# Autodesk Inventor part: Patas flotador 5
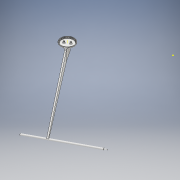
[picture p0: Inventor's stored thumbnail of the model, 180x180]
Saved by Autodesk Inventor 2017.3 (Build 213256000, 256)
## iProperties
Part Number: Patas flotador 5
Material: Plástico ABS
Document SubType Name: Modeling
Designer: PABLO HERNANDEZ
Density: 1.06 g/cm^3
Appearance: Suave - Blanco
Mass: 4.28877 g
Surface Area: 39.5254 cm^2
Volume: 4.04601 cm^3
Author: M.RICO
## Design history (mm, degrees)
sketch "Boceto1"
  geometry: C1 r 16 at (0, 0); 1 further point
  constraints: 1 centre point, 1 coincident
  dimensions: "d0" = 32 diameter of C1
extrude "Extrusión1" new body sketch "Boceto1" distance "d1" = 1; taper "d2" = 0 deg; dims "d93" = 1, "d94" = 0
sketch "Boceto2"
  geometry: C1 r 16 at (0, 0); C2 r 15 at (0, 0); C3 r 14 at (0, 0); 1 further point
  constraints: 3 centre point, 1 coincident
  dimensions: "d3" = 1 radial gap between concentric circles of C1 C2; "d4" = 1 radial gap between concentric circles of C2 C3
extrude "Extrusión2" join sketch "Boceto2" distance "d5" = 3; taper "d6" = 0 deg
sketch "Boceto3"
  geometry: C1 r 15 at (0, 0); C2 r 14 at (0, 0); 1 further point
  constraints: 2 centre point, 1 coincident
  dimensions: "d7" = 1 radial gap between concentric circles of C1 C2; "d123" = 30 diameter of C1
extrude "Extrusión3" join sketch "Boceto3" distance "d8" = 2; taper "d9" = 0 deg
sketch "Boceto4"
  geometry: C1 r 16 at (0, 0); 1 further point
  constraints: 1 centre point, 1 coincident
extrude "Extrusión4" cut sketch "Boceto4" distance "d10" = 0.5; taper "d11" = 0 deg
sketch "Boceto7"
  geometry: L1 (1.5, -15.93)-(1.5, 15.93); L2 (-1.5, -15.93)-(-1.5, 15.93); A1 r 16 centre (0, 0) between (1.5, 15.93) and (-1.5, 15.93); A2 r 16 centre (0, 0) between (-1.5, -15.93) and (1.5, -15.93); 2 further points
  constraints: 4 end point, 4 point on circle, 2 centre point, 1 coincident
extrude "Extrusión7" join sketch "Boceto7" distance "d63" = 25; taper "d64" = 0 deg
fillet "Empalme2" dims "d95" = 3
fillet "Empalme3" dims "d96" = 0.5
sketch "Boceto13"
  geometry: C1 r 1.2 at (-6, 0) reference; C2 r 1.75 at (-6, 0); C3 r 1.2 at (6, 0) reference; C4 r 1.75 at (6, 0); 1 further point
  constraints: 2 centre point, 2 coincident
  dimensions: "d118" = 3.5 diameter of C2; "d119" = 3.5 diameter of C4
extrude "Extrusión10" join sketch "Boceto13" distance "d120" = 3; taper "d121" = 0 deg
fillet "Empalme4" dims "d122" = 1
sketch "Boceto14"
  geometry: 1 further point
sketch "Boceto15"
  geometry: C1 r 1.2 at (6, 0) reference; C2 r 2.5 at (6, 0); C3 r 1.2 at (-6, 0) reference; C4 r 2.5 at (-6, 0); 1 further point
  constraints: 2 centre point, 2 coincident
  dimensions: "d124" = 5 diameter of C2; "d125" = 5 diameter of C4
extrude "Extrusión11" cut sketch "Boceto15" distance "d126" = 10; taper "d127" = 0 deg
hole "Agujero7" diameter "d151" = 2.4; stored, may be unused: countersink angle "d155" = 90 deg, drill point angle "d157" = 118 deg; dims "d149" = 10, "d150" = 10, "d152" = 6, "d153" = 4, "d154" = 2, "d156" = 8
hole "Agujero8" diameter "d160" = 2.4; stored, may be unused: countersink angle "d164" = 90 deg, drill point angle "d166" = 118 deg; dims "d158" = 10, "d159" = 10, "d161" = 6, "d162" = 4, "d163" = 2, "d165" = 8
node "Eje de trabajo1"
feature "Desplazar cuerpo1"
feature "Compuesta1"
feature "Desplazar cuerpo2"
node "Eje de trabajo2"
feature "Desplazar cuerpo3"
node "Plano de trabajo6"
sketch "Boceto27"
  geometry: L1 (0, 0)-(-149.324, -102.291); L2 (-134.431, -229.557)-(132.044, -87.232); C1 r 14 at (-149.324, -102.291) reference
  constraints: 4 end point
node "Plano de trabajo7"
node "Plano de trabajo8"
sketch "Boceto28"
  geometry: C1 r 2 at (0, 0); 1 further point
  constraints: 1 centre point
  dimensions: "d177" = 4 diameter of C1
extrude "Extrusión14" join sketch "Boceto28" stored distance "d178" = 10; taper "d179" = 0 deg
sketch "Boceto29"
  geometry: L1 (-0.28, 0)-(0, 0) reference; L2 (0, 0)-(-102.216, -91.987); L3 (-0.28, 23.165)-(-0.28, 0) reference; L4 (0, 23.165)-(0, 0) reference; L5 (0, 0)-(0, 23.165); L6 (0, 23.165)-(-105.015, -89.134); C1 r 2 at (-103.554, -90.5) reference; A1 r 2 centre (-103.554, -90.5) between (-102.216, -91.987) and (-105.015, -89.134) reference; 1 further point
  constraints: 6 end point, 2 point on circle, 2 tangent, 1 collinear
extrude "Extrusión15" join sketch "Boceto29" stored distance "d180" = 10; taper "d181" = 0 deg
node "Plano de trabajo9"
sketch "Boceto30"
  geometry: L1 (1.356, 23.165)-(1.356, 0) reference; L2 (1.356, 0)-(-130.469, -92.139); L3 (1.356, 0)-(1.356, 23.165); L4 (1.356, 23.165)-(-132.897, -88.965); A1 r 2 centre (-131.615, -90.5) between (-130.469, -92.139) and (-132.897, -88.965) reference; A2 r 2 centre (-131.615, -90.5) between (-132.897, -88.965) and (-130.469, -92.139); 1 further point
  constraints: 6 end point, 4 point on circle, 2 tangent, 1 centre point, 1 coincident, 1 vertical
extrude "Extrusión16" join sketch "Boceto30" distance "d182" = 3; taper "d183" = 0 deg
node "Plano de trabajo11"
sketch "Boceto31"
  geometry: L1 (-3.903, -5.958)-(206.564, -5.958); L2 (206.564, -5.958)-(206.564, 135.04); L3 (206.564, 135.04)-(-3.903, 135.04); L4 (-3.903, 135.04)-(-3.903, -5.958); 1 further point
  constraints: 8 end point, 2 parallel, 1 horizontal, 1 perpendicular
extrude "Extrusión17" cut sketch "Boceto31" distance "d186" = 200; taper "d187" = 0 deg
sketch "Boceto32"
  geometry: C1 r 2 at (0, 0) reference; C2 r 1 at (0, 0); 1 further point
  constraints: 1 centre point
  dimensions: "d188" = 1 radial gap between concentric circles of C1 C2
extrude "Extrusión18" cut sketch "Boceto32" distance "d189" = 6; taper "d190" = 0 deg
node "Sólido1"
node "Sup1"
other parameters: "sa_0" = 4, "d167" = 90 deg, "d168" = -149.324, "d169" = -102.291, "d170" = 0, "d171" = 9.86699, "d185" = 153
